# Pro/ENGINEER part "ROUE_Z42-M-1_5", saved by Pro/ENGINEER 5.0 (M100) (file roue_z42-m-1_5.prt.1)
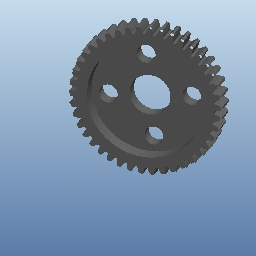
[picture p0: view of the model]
Units: millimeter Newton Second (mmNs); MM, TONNE, SECS
Materials in the file: NYLON

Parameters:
  PTC_MATERIAL_NAME = "NYLON"

Other named items: ROUE_Z42-M-1_5

Layers: 05_SURFACES, 06_REPERES, LAYER_11462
